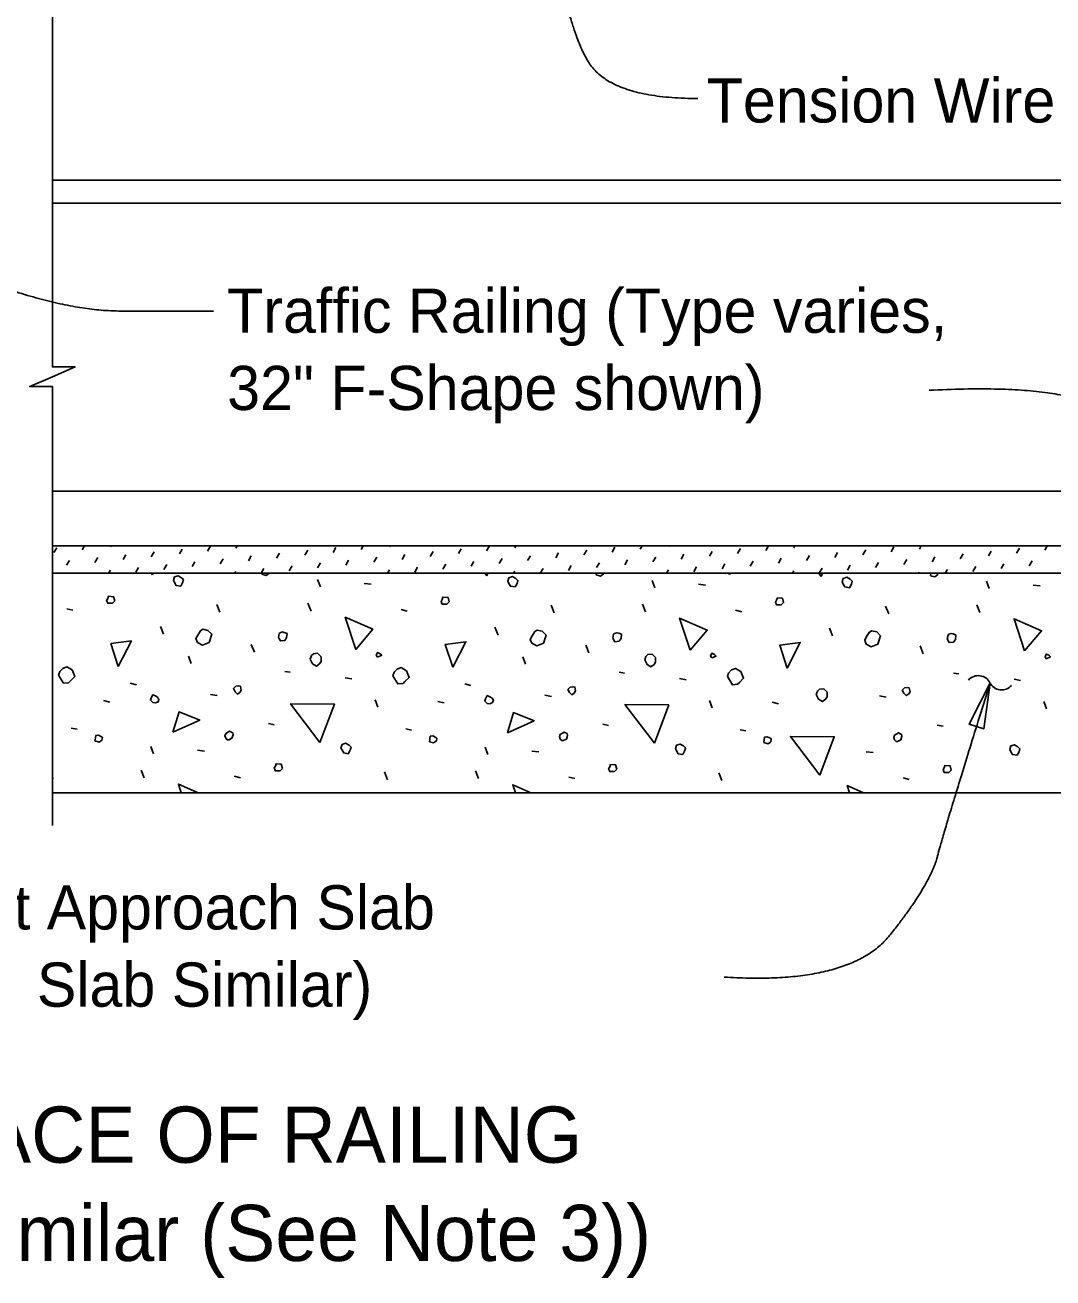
# Model space of a CAD drawing. Extents: x 0 to 41, y -96 to 25.
# Drawn here: x 16.13 to 20.81, y -84.87 to -79.16 of the extents above; entities that cross this region are included whole.
import ezdxf

# ---------------------------------------------------------------- set-up
doc = ezdxf.new("R2010")
doc.units = 0
for name, color, linetype in [('Dimension', 7, 'Continuous'), ('Miscellaneous', 7, 'Continuous'), ('SupstrConc', 7, 'Continuous'), ('SupstrConc_h', 7, 'Continuous'), ('TextStructures', 7, 'Continuous')]:
    doc.layers.add(name, color=color, linetype=linetype)

msp = doc.modelspace()

# ---------------------------------------------------------------- linework, layer by layer
at = {"layer": 'Dimension'}
msp.add_lwpolyline([(16.252, -78.863), (16.252, -80.7139), (16.3553, -80.7139), (16.252, -80.7589), (16.1487, -80.8039), (16.252, -80.8039), (16.252, -82.8047)], dxfattribs=at)
msp.add_lwpolyline([(20.5246, -82.1538), (20.4289, -82.3421), (20.4962, -82.3631)], close=True, dxfattribs=at)
for centre, start, end in [((20.4706, -82.1806), 26.8413, 138.5686), ((20.577, -82.1268), 206.8413, 318.5686)]:
    msp.add_arc(centre, 0.0596, start, end, dxfattribs=at)
for points in [[(19.1927, -79.4904), (18.7949, -79.4904), (18.5909, -79.1534), (18.5297, -78.6965)], [(16.9853, -80.4594), (16.9154, -80.4594), (16.2159, -80.4594), (15.6583, -80.2024)], [(20.2473, -80.8201), (20.836, -80.7917), (21.1574, -80.9999), (21.234, -81.0111)], [(19.3131, -83.4954), (19.886, -83.5319), (20.2509, -83.0752), (20.3172, -82.8179), (20.5245, -82.1539)]]:
    msp.add_open_spline(points, degree=2, dxfattribs=at)
at = {"layer": 'Miscellaneous'}
for p, q in [((16.2587, -81.5605), (16.2717, -81.5381)), ((16.3872, -81.5475), (16.3975, -81.5298)), ((16.5157, -81.5345), (16.5184, -81.5298)), ((16.8303, -81.5663), (16.8433, -81.544)), ((16.9588, -81.5534), (16.9717, -81.531)), ((17.0872, -81.5404), (17.0934, -81.5298)), ((17.4019, -81.5722), (17.4149, -81.5498)), ((17.5303, -81.5593), (17.5433, -81.5369)), ((17.6588, -81.5463), (17.6684, -81.5298)), ((17.7873, -81.5333), (17.7893, -81.5298)), ((18.1019, -81.5652), (18.1149, -81.5428)), ((18.2304, -81.5522), (18.2433, -81.5298)), ((18.3588, -81.5392), (18.3643, -81.5298)), ((18.6735, -81.5711), (18.6865, -81.5487)), ((18.802, -81.5581), (18.8149, -81.5357)), ((18.9304, -81.5451), (18.9393, -81.5298)), ((19.0589, -81.5322), (19.0603, -81.5298)), ((19.2451, -81.577), (19.258, -81.5546)), ((19.3735, -81.564), (19.3865, -81.5416)), ((19.502, -81.551), (19.5143, -81.5298)), ((19.6305, -81.5381), (19.6353, -81.5298)), ((19.9451, -81.5699), (19.9581, -81.5475)), ((20.0736, -81.5569), (20.0865, -81.5345)), ((20.202, -81.544), (20.2103, -81.5298)), ((20.3305, -81.531), (20.3312, -81.5298)), ((20.5167, -81.5758), (20.5297, -81.5534)), ((20.6452, -81.5628), (20.6581, -81.5404)), ((20.7736, -81.5498), (20.7852, -81.5298)), ((16.3165, -81.6182), (16.3294, -81.5958)), ((16.4449, -81.6052), (16.4579, -81.5828)), ((16.5734, -81.5923), (16.5864, -81.5699)), ((16.7019, -81.5793), (16.7148, -81.5569)), ((16.8881, -81.6241), (16.901, -81.6017)), ((17.0165, -81.6111), (17.0295, -81.5887)), ((17.145, -81.5982), (17.1579, -81.5758)), ((17.2734, -81.5852), (17.2864, -81.5628)), ((17.4596, -81.63), (17.4726, -81.6076)), ((17.5881, -81.617), (17.6011, -81.5946)), ((17.7166, -81.6041), (17.7295, -81.5817)), ((17.845, -81.5911), (17.858, -81.5687)), ((17.9735, -81.5781), (17.9864, -81.5557)), ((18.1597, -81.6229), (18.1726, -81.6005)), ((18.2881, -81.6099), (18.3011, -81.5876)), ((18.4166, -81.597), (18.4296, -81.5746)), ((18.545, -81.584), (18.558, -81.5616)), ((18.7313, -81.6288), (18.7442, -81.6064)), ((18.8597, -81.6158), (18.8727, -81.5934)), ((18.9882, -81.6029), (19.0011, -81.5805)), ((19.1166, -81.5899), (19.1296, -81.5675)), ((19.4313, -81.6217), (19.4443, -81.5993)), ((19.5597, -81.6088), (19.5727, -81.5864)), ((19.6882, -81.5958), (19.7012, -81.5734)), ((19.8167, -81.5828), (19.8296, -81.5605)), ((20.0029, -81.6276), (20.0158, -81.6052)), ((20.1313, -81.6147), (20.1443, -81.5923)), ((20.2598, -81.6017), (20.2727, -81.5793)), ((20.3882, -81.5887), (20.4012, -81.5663)), ((20.5744, -81.6335), (20.5874, -81.6111)), ((20.7029, -81.6206), (20.7159, -81.5982)), ((16.5075, -81.6547), (16.5157, -81.6406)), ((16.6311, -81.65), (16.6441, -81.6276)), ((16.7596, -81.6371), (16.7726, -81.6147)), ((17.0825, -81.6547), (17.0872, -81.6465)), ((17.2034, -81.6547), (17.2157, -81.6335)), ((17.3312, -81.6429), (17.3441, -81.6206)), ((17.6574, -81.6547), (17.6588, -81.6524)), ((17.7784, -81.6547), (17.7873, -81.6394)), ((17.9028, -81.6488), (17.9157, -81.6264)), ((18.0312, -81.6359), (18.0442, -81.6135)), ((18.3534, -81.6547), (18.3588, -81.6453)), ((18.4743, -81.6547), (18.4873, -81.6323)), ((18.6028, -81.6418), (18.6158, -81.6194)), ((19.0493, -81.6547), (19.0589, -81.6382)), ((19.1744, -81.6477), (19.1873, -81.6253)), ((19.3028, -81.6347), (19.3158, -81.6123)), ((19.6243, -81.6547), (19.6305, -81.6441)), ((19.746, -81.6536), (19.7589, -81.6312)), ((19.8744, -81.6406), (19.8874, -81.6182)), ((20.1993, -81.6547), (20.202, -81.65)), ((20.3203, -81.6547), (20.3305, -81.6371)), ((20.446, -81.6465), (20.459, -81.6241)), ((17.4727, -81.7171), (17.4603, -81.6836)), ((17.6725, -81.7012), (17.7043, -81.7048)), ((18.9965, -81.7207), (18.9841, -81.6871)), ((19.1963, -81.7048), (19.2281, -81.7083)), ((20.5203, -81.7242), (20.508, -81.6906)), ((20.7201, -81.7083), (20.7519, -81.7118)), ((16.3166, -81.8161), (16.3449, -81.8232)), ((17.0148, -81.832), (17.0007, -81.7967)), ((17.4303, -81.8267), (17.4161, -81.7914)), ((17.8404, -81.8197), (17.8687, -81.8267)), ((18.5387, -81.8356), (18.5245, -81.8002)), ((18.9541, -81.8303), (18.9399, -81.7949)), ((19.3642, -81.8232), (19.3925, -81.8303)), ((20.0625, -81.8391), (20.0483, -81.8038)), ((20.4779, -81.8338), (20.4638, -81.7985)), ((16.7585, -81.9328), (16.7444, -81.8975)), ((18.2823, -81.9363), (18.2682, -81.901)), ((19.8062, -81.9399), (19.792, -81.9045)), ((17.1722, -82.0141), (17.158, -81.9788)), ((18.696, -82.0177), (18.6819, -81.9823)), ((20.2198, -82.0212), (20.2057, -81.9858)), ((16.884, -82.0654), (16.8717, -82.0318)), ((18.4078, -82.0689), (18.3955, -82.0353)), ((17.3101, -82.1025), (17.3348, -82.106)), ((18.8339, -82.106), (18.8586, -82.1096)), ((20.3577, -82.1096), (20.3824, -82.1131)), ((16.6065, -82.1555), (16.6348, -82.1626)), ((17.5858, -82.1308), (17.6159, -82.1361)), ((18.1303, -82.1591), (18.1586, -82.1662)), ((19.1097, -82.1343), (19.1397, -82.1396)), ((20.6335, -82.1379), (20.6635, -82.1432)), ((16.4845, -82.2351), (16.5128, -82.2422)), ((16.9724, -82.2068), (17.0025, -82.2121)), ((17.7343, -82.2651), (17.722, -82.2316)), ((18.0083, -82.2386), (18.0366, -82.2457)), ((18.4962, -82.2103), (18.5263, -82.2157)), ((19.2581, -82.2687), (19.2458, -82.2351)), ((20.0201, -82.2139), (20.0501, -82.2192)), ((20.782, -82.2722), (20.7696, -82.2386)), ((19.5321, -82.2422), (19.5604, -82.2492)), ((17.2358, -82.3394), (17.2623, -82.3447)), ((18.7596, -82.3429), (18.7862, -82.3482)), ((20.2834, -82.3465), (20.31, -82.3518)), ((16.3378, -82.3606), (16.3643, -82.3659)), ((17.8616, -82.3641), (17.8881, -82.3694)), ((19.3854, -82.3677), (19.4119, -82.373)), ((16.7126, -82.4773), (16.7002, -82.4437)), ((16.9123, -82.4614), (16.9441, -82.4649)), ((18.2364, -82.4808), (18.224, -82.4472)), ((18.4361, -82.4649), (18.468, -82.4684)), ((19.9599, -82.4684), (19.9918, -82.472)), ((16.6701, -82.5869), (16.656, -82.5515)), ((17.0803, -82.5798), (17.1085, -82.5869)), ((17.7785, -82.5957), (17.7644, -82.5604)), ((18.1939, -82.5904), (18.1798, -82.5551)), ((19.3023, -82.5993), (19.2882, -82.5639)), ((16.2547, -82.5922), (16.252, -82.5853)), ((18.6041, -82.5833), (18.6324, -82.5904)), ((20.1279, -82.5869), (20.1562, -82.594))]:
    msp.add_line(p, q, dxfattribs=at)
for points in [[(16.7073, -81.6623), (16.7015, -81.6547)], [(16.7101, -81.6547), (16.7073, -81.6623)], [(16.8063, -81.6942), (16.8151, -81.7101), (16.8363, -81.7136), (16.8451, -81.6977), (16.8487, -81.6836), (16.8398, -81.6747), (16.8239, -81.6659), (16.808, -81.6712), (16.8027, -81.6871), (16.8063, -81.6942)], [(17.2058, -81.6588), (17.2252, -81.6641), (17.2376, -81.6553), (17.2377, -81.6547)], [(17.2063, -81.6547), (17.2058, -81.6588)], [(18.2311, -81.6659), (18.2226, -81.6547)], [(18.2352, -81.6547), (18.2311, -81.6659)], [(18.7296, -81.6623), (18.749, -81.6676), (18.7614, -81.6588), (18.762, -81.6547)], [(18.7307, -81.6547), (18.7296, -81.6623)], [(19.3301, -81.6547), (19.3324, -81.657)], [(19.3324, -81.657), (19.3395, -81.657), (19.3441, -81.6547)], [(19.7549, -81.6694), (19.7437, -81.6547)], [(19.7604, -81.6547), (19.7549, -81.6694)], [(20.2534, -81.6659), (20.2728, -81.6712), (20.2852, -81.6623), (20.2863, -81.6547)], [(20.255, -81.6547), (20.2534, -81.6659)], [(18.3301, -81.6977), (18.3389, -81.7136), (18.3601, -81.7171), (18.369, -81.7012), (18.3725, -81.6871), (18.3637, -81.6782), (18.3477, -81.6694), (18.3318, -81.6747), (18.3265, -81.6906), (18.3301, -81.6977)], [(19.8539, -81.7012), (19.8627, -81.7171), (19.8839, -81.7207), (19.8928, -81.7048), (19.8963, -81.6906), (19.8875, -81.6818), (19.8716, -81.6729), (19.8556, -81.6782), (19.8503, -81.6942), (19.8539, -81.7012)], [(16.504, -81.7914), (16.5252, -81.7914), (16.5358, -81.7808), (16.5305, -81.7613), (16.5075, -81.7596), (16.504, -81.7702), (16.4987, -81.779), (16.504, -81.7914), (16.5004, -81.7879)], [(18.0278, -81.7949), (18.049, -81.7949), (18.0596, -81.7843), (18.0543, -81.7649), (18.0313, -81.7631), (18.0278, -81.7737), (18.0225, -81.7825), (18.0278, -81.7949), (18.0242, -81.7914)], [(19.5516, -81.7985), (19.5728, -81.7985), (19.5834, -81.7879), (19.5781, -81.7684), (19.5551, -81.7666), (19.5516, -81.7772), (19.5463, -81.7861), (19.5516, -81.7985), (19.5481, -81.7949)], [(17.6336, -82.0018), (17.5858, -81.855), (17.7113, -81.9098), (17.6336, -82.0018)], [(19.1574, -82.0053), (19.1097, -81.8586), (19.2352, -81.9134), (19.1574, -82.0053)], [(20.6812, -82.0088), (20.6335, -81.8621), (20.759, -81.9169), (20.6812, -82.0088)], [(16.9123, -81.9699), (16.9353, -81.9823), (16.9654, -81.9699), (16.9777, -81.9328), (16.96, -81.9151), (16.9371, -81.9098), (16.9265, -81.9169), (16.9141, -81.9363), (16.9052, -81.9523), (16.9123, -81.9699)], [(17.2818, -81.9469), (17.2906, -81.9629), (17.3101, -81.9611), (17.3189, -81.9487), (17.3207, -81.9293), (17.3083, -81.924), (17.2995, -81.9222), (17.2889, -81.9257), (17.2853, -81.9293), (17.2818, -81.9469)], [(18.4361, -81.9735), (18.4591, -81.9858), (18.4892, -81.9735), (18.5015, -81.9363), (18.4839, -81.9187), (18.4609, -81.9134), (18.4503, -81.9204), (18.4379, -81.9399), (18.4291, -81.9558), (18.4361, -81.9735)], [(18.8056, -81.9505), (18.8144, -81.9664), (18.8339, -81.9646), (18.8427, -81.9523), (18.8445, -81.9328), (18.8321, -81.9275), (18.8233, -81.9257), (18.8127, -81.9293), (18.8091, -81.9328), (18.8056, -81.9505)], [(19.9599, -81.977), (19.9829, -81.9894), (20.013, -81.977), (20.0254, -81.9399), (20.0077, -81.9222), (19.9847, -81.9169), (19.9741, -81.924), (19.9617, -81.9434), (19.9529, -81.9593), (19.9599, -81.977)], [(20.3294, -81.954), (20.3382, -81.9699), (20.3577, -81.9682), (20.3665, -81.9558), (20.3683, -81.9363), (20.3559, -81.931), (20.3471, -81.9293), (20.3365, -81.9328), (20.3329, -81.9363), (20.3294, -81.954)], [(16.5517, -82.0795), (16.5181, -81.9752), (16.6118, -81.9629), (16.5517, -82.0795)], [(18.0755, -82.0831), (18.0419, -81.9788), (18.1356, -81.9664), (18.0755, -82.0831)], [(19.5993, -82.0866), (19.5657, -81.9823), (19.6594, -81.9699), (19.5993, -82.0866)], [(17.4267, -82.0459), (17.4373, -82.0672), (17.455, -82.0778), (17.4692, -82.0672), (17.4762, -82.0566), (17.4762, -82.0353), (17.4603, -82.0194), (17.4409, -82.0212), (17.432, -82.03), (17.4267, -82.0459)], [(17.7326, -82.0371), (17.752, -82.0283), (17.7449, -82.0212), (17.7326, -82.0159), (17.7273, -82.0283), (17.7326, -82.0371)], [(18.9506, -82.0495), (18.9612, -82.0707), (18.9788, -82.0813), (18.993, -82.0707), (19.0001, -82.0601), (19.0001, -82.0389), (18.9841, -82.023), (18.9647, -82.0247), (18.9559, -82.0336), (18.9506, -82.0495)], [(19.2564, -82.0406), (19.2758, -82.0318), (19.2688, -82.0247), (19.2564, -82.0194), (19.2511, -82.0318), (19.2564, -82.0406)], [(20.7802, -82.0442), (20.7996, -82.0353), (20.7926, -82.0283), (20.7802, -82.023), (20.7749, -82.0353), (20.7802, -82.0442)], [(16.2795, -82.1184), (16.3024, -82.1555), (16.3254, -82.1538), (16.3343, -82.1449), (16.3537, -82.1255), (16.3413, -82.0954), (16.3166, -82.0813), (16.2989, -82.0884), (16.2848, -82.1025), (16.2795, -82.1184)], [(17.8033, -82.122), (17.8263, -82.1591), (17.8492, -82.1573), (17.8581, -82.1485), (17.8775, -82.129), (17.8651, -82.099), (17.8404, -82.0848), (17.8227, -82.0919), (17.8086, -82.106), (17.8033, -82.122)], [(19.3271, -82.1255), (19.3501, -82.1626), (19.373, -82.1608), (19.3819, -82.152), (19.4013, -82.1326), (19.389, -82.1025), (19.3642, -82.0884), (19.3465, -82.0954), (19.3324, -82.1096), (19.3271, -82.1255)], [(17.0838, -82.1944), (17.0944, -82.205), (17.105, -82.198), (17.1121, -82.1874), (17.1085, -82.1697), (17.0997, -82.1679), (17.0873, -82.1697), (17.0767, -82.1803), (17.0838, -82.1944)], [(18.6076, -82.198), (18.6182, -82.2086), (18.6288, -82.2015), (18.6359, -82.1909), (18.6324, -82.1732), (18.6235, -82.1715), (18.6111, -82.1732), (18.6005, -82.1838), (18.6076, -82.198)], [(19.7325, -82.2077), (19.7431, -82.2289), (19.7608, -82.2395), (19.7749, -82.2289), (19.782, -82.2183), (19.782, -82.1971), (19.7661, -82.1811), (19.7467, -82.1829), (19.7378, -82.1918), (19.7325, -82.2077)], [(20.1314, -82.2015), (20.142, -82.2121), (20.1526, -82.205), (20.1597, -82.1944), (20.1562, -82.1768), (20.1473, -82.175), (20.135, -82.1768), (20.1244, -82.1874), (20.1314, -82.2015)], [(16.709, -82.2439), (16.7214, -82.2457), (16.7338, -82.2404), (16.7373, -82.2298), (16.732, -82.221), (16.7214, -82.2139), (16.709, -82.2086), (16.702, -82.2227), (16.6984, -82.2333), (16.709, -82.2439)], [(18.2328, -82.2475), (18.2452, -82.2492), (18.2576, -82.2439), (18.2611, -82.2333), (18.2558, -82.2245), (18.2452, -82.2174), (18.2328, -82.2121), (18.2258, -82.2263), (18.2222, -82.2369), (18.2328, -82.2475)], [(16.8009, -82.3783), (16.8292, -82.2864), (16.9229, -82.3235), (16.8009, -82.3783)], [(17.4709, -82.426), (17.3366, -82.2492), (17.5363, -82.251), (17.4709, -82.426)], [(18.3248, -82.3818), (18.353, -82.2899), (18.4467, -82.327), (18.3248, -82.3818)], [(18.9947, -82.4296), (18.8604, -82.2528), (19.0602, -82.2545), (18.9947, -82.4296)], [(16.4456, -82.4189), (16.4651, -82.4242), (16.4774, -82.4154), (16.4792, -82.403), (16.4757, -82.3995), (16.4615, -82.3924), (16.4492, -82.3942), (16.4474, -82.4066), (16.4456, -82.4189)], [(17.0484, -82.4136), (17.0555, -82.4136), (17.0696, -82.4066), (17.075, -82.3907), (17.0732, -82.3818), (17.059, -82.3747), (17.0414, -82.3854), (17.0378, -82.396), (17.0414, -82.4066), (17.0484, -82.4136)], [(17.9694, -82.4225), (17.9889, -82.4278), (18.0013, -82.4189), (18.003, -82.4066), (17.9995, -82.403), (17.9854, -82.396), (17.973, -82.3977), (17.9712, -82.4101), (17.9694, -82.4225)], [(18.5723, -82.4172), (18.5793, -82.4172), (18.5935, -82.4101), (18.5988, -82.3942), (18.597, -82.3854), (18.5829, -82.3783), (18.5652, -82.3889), (18.5616, -82.3995), (18.5652, -82.4101), (18.5723, -82.4172)], [(19.4933, -82.426), (19.5127, -82.4313), (19.5251, -82.4225), (19.5268, -82.4101), (19.5233, -82.4066), (19.5092, -82.3995), (19.4968, -82.4013), (19.495, -82.4136), (19.4933, -82.426)], [(19.7486, -82.5749), (19.6143, -82.3981), (19.814, -82.3999), (19.7486, -82.5749)], [(20.0961, -82.4207), (20.1031, -82.4207), (20.1173, -82.4136), (20.1226, -82.3977), (20.1208, -82.3889), (20.1067, -82.3818), (20.089, -82.3924), (20.0855, -82.403), (20.089, -82.4136), (20.0961, -82.4207)], [(17.5699, -82.4578), (17.5788, -82.4737), (17.6, -82.4773), (17.6088, -82.4614), (17.6124, -82.4472), (17.6035, -82.4384), (17.5876, -82.4296), (17.5717, -82.4349), (17.5664, -82.4508), (17.5699, -82.4578)], [(19.0937, -82.4614), (19.1026, -82.4773), (19.1238, -82.4808), (19.1326, -82.4649), (19.1362, -82.4508), (19.1273, -82.4419), (19.1114, -82.4331), (19.0955, -82.4384), (19.0902, -82.4543), (19.0937, -82.4614)], [(20.6176, -82.4649), (20.6264, -82.4808), (20.6476, -82.4844), (20.6564, -82.4684), (20.66, -82.4543), (20.6511, -82.4455), (20.6352, -82.4366), (20.6193, -82.4419), (20.614, -82.4578), (20.6176, -82.4649)], [(17.2676, -82.5551), (17.2889, -82.5551), (17.2995, -82.5445), (17.2942, -82.525), (17.2712, -82.5232), (17.2676, -82.5338), (17.2623, -82.5427), (17.2676, -82.5551), (17.2641, -82.5515)], [(18.7915, -82.5586), (18.8127, -82.5586), (18.8233, -82.548), (18.818, -82.5285), (18.795, -82.5268), (18.7915, -82.5374), (18.7862, -82.5462), (18.7915, -82.5586), (18.7879, -82.5551)], [(20.3153, -82.5621), (20.3365, -82.5621), (20.3471, -82.5515), (20.3418, -82.5321), (20.3188, -82.5303), (20.3153, -82.5409), (20.31, -82.5498), (20.3153, -82.5621), (20.3117, -82.5586)], [(16.8386, -82.6547), (16.8257, -82.6152), (16.9163, -82.6547)], [(18.3612, -82.6547), (18.3495, -82.6187), (18.432, -82.6547)], [(19.8839, -82.6547), (19.8733, -82.6222), (19.9477, -82.6547)]]:
    msp.add_lwpolyline(points, dxfattribs=at)
at = {"layer": 'SupstrConc'}
for p, q in [((16.252, -79.8631), (23.5538, -79.8631)), ((16.252, -79.9673), (23.5538, -79.9673)), ((16.252, -81.5298), (23.5538, -81.5298)), ((21.5538, -81.6547), (16.252, -81.6547)), ((21.9365, -82.6547), (16.252, -82.6547))]:
    msp.add_line(p, q, dxfattribs=at)
at = {"layer": 'SupstrConc_h'}
msp.add_line((16.252, -81.2797), (23.5538, -81.2797), dxfattribs=at)

# ---------------------------------------------------------------- texts
at = {"layer": 'Dimension'}
for s, height, p in [('Traffic Railing (Type varies,', 0.2016, (17.0479, -80.5585)), ('32" F-Shape shown)', 0.2016, (17.0479, -80.9105)), ('Approach Slab (Flexible Pavement Approach Slab ', 0.2016, (11.9999, -83.2783)), ('Shown, Rigid Pavement Approach Slab Similar)', 0.2016, (11.9999, -83.6303)), ('ELEVATION OF OUTSIDE FACE OF RAILING', 0.256001, (11.5134, -84.3415)), ('(Traffic Railing Shown, Concrete Parapet Similar (See Note 3))', 0.256001, (9.4668, -84.7895))]:
    msp.add_text(s, height=height, dxfattribs=at).set_placement(p)
at = {"layer": 'TextStructures'}
msp.add_text('Tension Wire', height=0.2016, dxfattribs=at).set_placement((19.2335, -79.5999))

doc.saveas('drawing.dxf')
